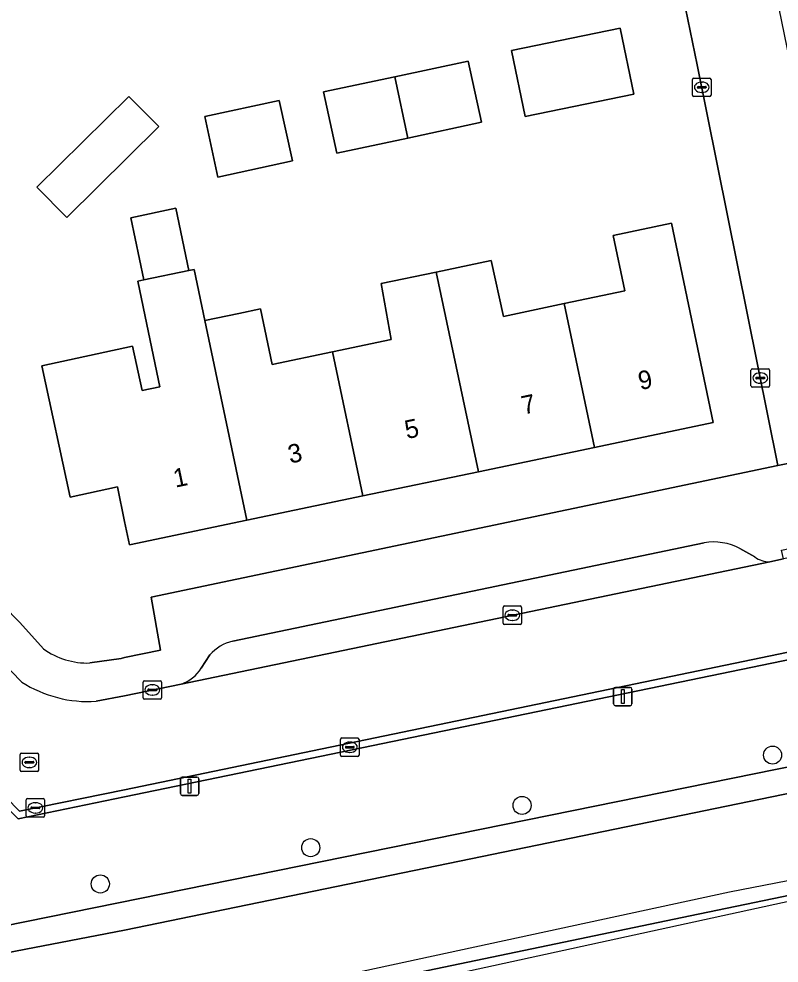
# Model space of a CAD drawing. Extents: x 162879 to 165540, y 384011 to 385181.
# Drawn here: x 163994.3 to 164035.4, y 384179.7 to 384230.8 of the extents above; entities that cross this region are included whole.
import ezdxf

# ---------------------------------------------------------------- set-up
doc = ezdxf.new("R2010")
doc.units = 0
for name, color, linetype in [('IMGEO_Boom', 7, 'Continuous'), ('IMGEO_Erf', 7, 'Continuous'), ('IMGEO_Geluidsscherm', 7, 'Continuous'), ('IMGEO_Groenvoorziening', 7, 'Continuous'), ('IMGEO_Hek', 7, 'Continuous'), ('IMGEO_Kolk', 7, 'Continuous'), ('IMGEO_Lichtmast', 7, 'Continuous'), ('IMGEO_Pand', 7, 'Continuous'), ('IMGEO_Pand_nummerreeks', 7, 'Continuous'), ('IMGEO_Parkeervlak_open', 7, 'Continuous'), ('IMGEO_Rijbaan_lokaal_open', 7, 'Continuous'), ('IMGEO_Rioolput', 7, 'Continuous'), ('IMGEO_Spoorbaan_halfverhard', 7, 'Continuous'), ('IMGEO_Voetpad_open', 7, 'Continuous')]:
    doc.layers.add(name, color=color, linetype=linetype)

msp = doc.modelspace()

# ---------------------------------------------------------------- linework, layer by layer
at = {"layer": 'IMGEO_Boom'}
for centre in [(164035.048, 384190.943), (164021.499, 384188.217), (164010.068, 384185.932), (163998.687, 384183.967)]:
    msp.add_circle(centre, 0.489, dxfattribs=at)
at = {"layer": 'IMGEO_Erf'}
for points in [[(163998.128, 384195.926), (163999.82, 384196.177), (164000, 384196.214), (164001.949, 384196.619), (164001.432, 384199.492), (164035.326, 384206.609), (164030.966, 384228.287), (164030.221, 384231.993), (164030.024, 384232.973), (164025.891, 384232.23), (164024.866, 384233.172), (164020.603, 384237.498)], [(163991.514, 384230.806), (163992.767, 384225.971), (163990.535, 384223.775), (163989.018, 384225.098), (163987.035, 384223.137), (163984.673, 384225.525), (163982.432, 384223.309), (163980.176, 384221.078), (163982.517, 384218.711), (163981.927, 384218.127), (163978.371, 384214.611), (163978.245, 384214.739), (163978.172, 384214.67), (163984.509, 384208.134), (163994.326, 384198.122), (163995.611, 384196.7)]]:
    msp.add_lwpolyline(points, dxfattribs=at)
for points in [[(164026.81, 384230.281), (164027.548, 384226.704), (164021.672, 384225.491), (164020.934, 384229.068)], [(164018.592, 384228.499), (164019.301, 384225.185), (164015.319, 384224.333), (164011.476, 384223.51), (164010.767, 384226.824), (164014.618, 384227.648)], [(164001.844, 384224.953), (163996.873, 384220.038), (163995.26, 384221.669), (164000.231, 384226.584)], [(164009.075, 384223.094), (164005.045, 384222.219), (164004.334, 384225.495), (164008.364, 384226.37)], [(164026.428, 384219.065), (164029.576, 384219.725), (164031.839, 384208.942), (164025.412, 384207.593), (164019.139, 384206.276), (164012.881, 384204.963), (164006.619, 384203.649), (164000.265, 384202.315), (164000, 384203.589), (163999.613, 384205.451), (163997.059, 384204.896), (163995.516, 384212.008), (164000.432, 384213.074), (164000.955, 384210.665), (164001.909, 384210.863), (164001.289, 384213.817), (164000.708, 384216.585), (164001.048, 384216.657), (164000.342, 384220.023), (164002.773, 384220.533), (164003.48, 384217.167), (164003.755, 384217.225), (164004.339, 384214.458), (164006.183, 384214.845), (164007.36, 384215.092), (164007.991, 384212.087), (164011.242, 384212.769), (164014.418, 384213.435), (164013.875, 384216.457), (164016.853, 384217.082), (164019.835, 384217.707), (164020.497, 384214.682), (164023.785, 384215.372), (164027.058, 384216.059)]]:
    msp.add_lwpolyline(points, close=True, dxfattribs=at)
msp.add_arc((163997.992, 384199.963), 4.039, 233.8811, 271.9327, dxfattribs=at)
at = {"layer": 'IMGEO_Geluidsscherm'}
msp.add_lwpolyline([(164249.574, 384228.544), (164187.192, 384215.485), (164162.302, 384210.469), (164148.545, 384207.416), (164111.054, 384199.697), (164098.433, 384197.191), (164085.381, 384194.319), (164046.457, 384186.201), (164032.718, 384183.532), (164006.753, 384177.923), (163992.535, 384174.933), (163980.798, 384172.554), (163968.077, 384170.103), (163956.144, 384167.447), (163943.692, 384164.81), (163915.585, 384159)], dxfattribs=at)
at = {"layer": 'IMGEO_Groenvoorziening'}
for points in [[(164160.958, 384209.557), (164249.738, 384228.363), (164257.439, 384229.994), (164258.307, 384234.301), (164257.821, 384235.374), (164247.659, 384233.092), (164206.397, 384224.477), (164195.144, 384222.287), (164168.08, 384216.522), (164150.94, 384212.716), (164150.871, 384211.974), (164045.253, 384190.792), (164000, 384181.465), (163991.655, 384179.863), (163957.137, 384215.862)], [(163910.141, 384165.293), (163907.388, 384161.891), (163904.144, 384157.751), (163904.294, 384156.793), (163905.524, 384156.297), (163907.829, 384156.853), (163915.94, 384158.516), (163963.608, 384168.288), (164030.584, 384182.247), (164064.865, 384189.352), (164113.541, 384199.968), (164160.958, 384209.557)]]:
    msp.add_lwpolyline(points, dxfattribs=at)
for points in [[(164151.264, 384223.068), (164151.207, 384224.522), (164151.782, 384230.115), (164144.063, 384233.478), (164143.197, 384222.298), (164142.818, 384218.333), (164141.152, 384217.855), (164120.789, 384213.646), (164115.149, 384212.48), (164021.738, 384193.17), (164000, 384188.678), (163994.239, 384187.487), (163984.24, 384197.653), (163961.899, 384220.601), (163959.515, 384218.234), (163957.137, 384215.862), (163991.655, 384179.863), (163992.185, 384181.427), (164150.97, 384213.664)], [(164150.871, 384211.974), (164150.94, 384212.716), (164150.953, 384213.129), (164150.97, 384213.664), (163992.185, 384181.427), (163991.655, 384179.863), (164000, 384181.465), (164045.253, 384190.792)]]:
    msp.add_lwpolyline(points, close=True, dxfattribs=at)
at = {"layer": 'IMGEO_Hek'}
for points in [[(164000, 384181.465), (164045.253, 384190.792), (164150.871, 384211.974), (164150.94, 384212.716)], [(164064.865, 384189.352), (164030.584, 384182.247), (163963.608, 384168.288), (163907.829, 384156.853), (163905.524, 384156.297), (163904.294, 384156.793), (163904.144, 384157.751)], [(164000, 384181.465), (163991.655, 384179.863)]]:
    msp.add_lwpolyline(points, dxfattribs=at)
at = {"layer": 'IMGEO_Kolk'}
for p, q in [((164030.721, 384226.653), (164030.721, 384227.505)), ((164030.796, 384227.579), (164031.648, 384227.579)), ((164031.209, 384227.359), (164031.234, 384227.359)), ((164031.722, 384227.505), (164031.722, 384226.653)), ((164030.98, 384227.073), (164030.98, 384227.085)), ((164031.418, 384227.036), (164031.02, 384227.036)), ((164031.023, 384227.122), (164031.421, 384227.122)), ((164031.232, 384226.799), (164031.207, 384226.799)), ((164031.464, 384227.085), (164031.464, 384227.073)), ((164031.648, 384226.579), (164030.796, 384226.579)), ((164033.882, 384210.92), (164033.882, 384211.772)), ((164033.957, 384211.846), (164034.809, 384211.846)), ((164034.184, 384211.389), (164034.582, 384211.389)), ((164034.37, 384211.626), (164034.395, 384211.626)), ((164034.883, 384211.772), (164034.883, 384210.92)), ((164034.141, 384211.34), (164034.141, 384211.352)), ((164034.579, 384211.303), (164034.181, 384211.303)), ((164034.393, 384211.066), (164034.368, 384211.066)), ((164034.625, 384211.352), (164034.625, 384211.34)), ((164034.809, 384210.846), (164033.957, 384210.846)), ((164020.476, 384198.085), (164020.476, 384198.937)), ((164020.551, 384199.011), (164021.403, 384199.011)), ((164020.964, 384198.791), (164020.989, 384198.791)), ((164021.477, 384198.937), (164021.477, 384198.085)), ((164020.735, 384198.505), (164020.735, 384198.517)), ((164021.173, 384198.468), (164020.775, 384198.468)), ((164020.778, 384198.554), (164021.176, 384198.554)), ((164020.987, 384198.231), (164020.962, 384198.231)), ((164021.219, 384198.517), (164021.219, 384198.505)), ((164021.403, 384198.011), (164020.551, 384198.011)), ((164001.004, 384194.042), (164001.004, 384194.894)), ((164001.079, 384194.968), (164001.931, 384194.968)), ((164001.492, 384194.748), (164001.517, 384194.748)), ((164002.005, 384194.894), (164002.005, 384194.042)), ((164001.263, 384194.462), (164001.263, 384194.474)), ((164001.701, 384194.425), (164001.303, 384194.425)), ((164001.306, 384194.511), (164001.704, 384194.511)), ((164001.515, 384194.188), (164001.49, 384194.188)), ((164001.747, 384194.474), (164001.747, 384194.462)), ((164001.931, 384193.968), (164001.079, 384193.968)), ((164011.682, 384190.942), (164011.682, 384191.794)), ((164011.757, 384191.868), (164012.609, 384191.868)), ((164012.17, 384191.648), (164012.195, 384191.648)), ((164012.683, 384191.794), (164012.683, 384190.942)), ((164011.941, 384191.362), (164011.941, 384191.374)), ((164012.379, 384191.325), (164011.981, 384191.325)), ((164011.984, 384191.411), (164012.382, 384191.411)), ((164012.193, 384191.088), (164012.168, 384191.088)), ((164012.425, 384191.374), (164012.425, 384191.362)), ((164012.609, 384190.868), (164011.757, 384190.868)), ((163994.676, 384187.661), (163994.676, 384188.513)), ((163994.751, 384188.587), (163995.603, 384188.587)), ((163995.677, 384188.513), (163995.677, 384187.661)), ((163994.935, 384188.081), (163994.935, 384188.093)), ((163995.373, 384188.044), (163994.975, 384188.044)), ((163994.978, 384188.13), (163995.376, 384188.13)), ((163995.164, 384188.367), (163995.189, 384188.367)), ((163995.419, 384188.093), (163995.419, 384188.081)), ((163995.603, 384187.587), (163994.751, 384187.587)), ((163995.187, 384187.807), (163995.162, 384187.807))]:
    msp.add_line(p, q, dxfattribs=at)
for points in [[(164030.721, 384226.653), (164030.721, 384227.505)], [(164030.796, 384227.579), (164031.648, 384227.579)], [(164031.722, 384227.505), (164031.722, 384226.653)], [(164031.648, 384226.579), (164030.796, 384226.579)], [(164033.882, 384210.92), (164033.882, 384211.772)], [(164033.957, 384211.846), (164034.809, 384211.846)], [(164034.883, 384211.772), (164034.883, 384210.92)], [(164034.809, 384210.846), (164033.957, 384210.846)], [(164020.476, 384198.085), (164020.476, 384198.937)], [(164020.551, 384199.011), (164021.403, 384199.011)], [(164021.477, 384198.937), (164021.477, 384198.085)], [(164021.403, 384198.011), (164020.551, 384198.011)], [(164001.004, 384194.042), (164001.004, 384194.894)], [(164001.079, 384194.968), (164001.931, 384194.968)], [(164002.005, 384194.894), (164002.005, 384194.042)], [(164001.931, 384193.968), (164001.079, 384193.968)], [(164011.682, 384190.942), (164011.682, 384191.794)], [(164011.757, 384191.868), (164012.609, 384191.868)], [(164012.683, 384191.794), (164012.683, 384190.942)], [(164012.609, 384190.868), (164011.757, 384190.868)], [(163994.676, 384187.661), (163994.676, 384188.513)], [(163994.751, 384188.587), (163995.603, 384188.587)], [(163995.677, 384188.513), (163995.677, 384187.661)], [(163995.603, 384187.587), (163994.751, 384187.587)]]:
    msp.add_lwpolyline(points, dxfattribs=at)
for centre, radius, start, end in [((164030.798, 384227.503), 0.0765, 91.552, 178.448), ((164030.798, 384227.503), 0.0765, 91.552, 178.448), ((164031.646, 384227.503), 0.0765, 1.552, 88.448), ((164031.646, 384227.503), 0.0765, 1.552, 88.448), ((164031.02, 384227.082), 0.0403, 85.8775, 175.7526), ((164031.017, 384227.072), 0.0366, 178.938, 274.7102), ((164031.421, 384227.079), 0.043, 264.8664, 352.4533), ((164031.425, 384227.084), 0.0386, 1.7309, 96.639), ((164030.798, 384226.655), 0.0765, 181.552, 268.448), ((164030.798, 384226.655), 0.0765, 181.552, 268.448), ((164031.646, 384226.655), 0.0765, 271.552, 358.448), ((164031.646, 384226.655), 0.0765, 271.552, 358.448), ((164033.959, 384211.77), 0.0765, 91.552, 178.448), ((164033.959, 384211.77), 0.0765, 91.552, 178.448), ((164034.181, 384211.349), 0.0403, 85.8775, 175.7526), ((164034.586, 384211.351), 0.0386, 1.7309, 96.639), ((164034.807, 384211.77), 0.0765, 1.552, 88.448), ((164034.807, 384211.77), 0.0765, 1.552, 88.448), ((164033.959, 384210.922), 0.0765, 181.552, 268.448), ((164033.959, 384210.922), 0.0765, 181.552, 268.448), ((164034.178, 384211.339), 0.0366, 178.938, 274.7102), ((164034.582, 384211.346), 0.043, 264.8664, 352.4533), ((164034.807, 384210.922), 0.0765, 271.552, 358.448), ((164034.807, 384210.922), 0.0765, 271.552, 358.448), ((164020.553, 384198.935), 0.0765, 91.552, 178.448), ((164020.553, 384198.935), 0.0765, 91.552, 178.448), ((164021.401, 384198.935), 0.0765, 1.552, 88.448), ((164021.401, 384198.935), 0.0765, 1.552, 88.448), ((164020.775, 384198.514), 0.0403, 85.8775, 175.7526), ((164020.772, 384198.504), 0.0366, 178.938, 274.7102), ((164021.176, 384198.511), 0.043, 264.8664, 352.4533), ((164021.18, 384198.516), 0.0386, 1.7309, 96.639), ((164020.553, 384198.087), 0.0765, 181.552, 268.448), ((164020.553, 384198.087), 0.0765, 181.552, 268.448), ((164021.401, 384198.087), 0.0765, 271.552, 358.448), ((164021.401, 384198.087), 0.0765, 271.552, 358.448), ((164001.081, 384194.892), 0.0765, 91.552, 178.448), ((164001.081, 384194.892), 0.0765, 91.552, 178.448), ((164001.929, 384194.892), 0.0765, 1.552, 88.448), ((164001.929, 384194.892), 0.0765, 1.552, 88.448), ((164001.081, 384194.044), 0.0765, 181.552, 268.448), ((164001.081, 384194.044), 0.0765, 181.552, 268.448), ((164001.303, 384194.471), 0.0403, 85.8775, 175.7526), ((164001.3, 384194.461), 0.0366, 178.938, 274.7102), ((164001.704, 384194.468), 0.043, 264.8664, 352.4533), ((164001.708, 384194.473), 0.0386, 1.7309, 96.639), ((164001.929, 384194.044), 0.0765, 271.552, 358.448), ((164001.929, 384194.044), 0.0765, 271.552, 358.448), ((164011.759, 384191.792), 0.0765, 91.552, 178.448), ((164011.759, 384191.792), 0.0765, 91.552, 178.448), ((164012.607, 384191.792), 0.0765, 1.552, 88.448), ((164012.607, 384191.792), 0.0765, 1.552, 88.448), ((164011.759, 384190.944), 0.0765, 181.552, 268.448), ((164011.759, 384190.944), 0.0765, 181.552, 268.448), ((164011.981, 384191.371), 0.0403, 85.8775, 175.7526), ((164011.978, 384191.361), 0.0366, 178.938, 274.7102), ((164012.382, 384191.368), 0.043, 264.8664, 352.4533), ((164012.386, 384191.373), 0.0386, 1.7309, 96.639), ((164012.607, 384190.944), 0.0765, 271.552, 358.448), ((164012.607, 384190.944), 0.0765, 271.552, 358.448), ((163994.753, 384188.511), 0.0765, 91.552, 178.448), ((163994.753, 384188.511), 0.0765, 91.552, 178.448), ((163995.601, 384188.511), 0.0765, 1.552, 88.448), ((163995.601, 384188.511), 0.0765, 1.552, 88.448), ((163994.975, 384188.09), 0.0403, 85.8775, 175.7526), ((163994.972, 384188.08), 0.0366, 178.938, 274.7102), ((163995.376, 384188.087), 0.043, 264.8664, 352.4533), ((163995.38, 384188.092), 0.0386, 1.7309, 96.639), ((163994.753, 384187.663), 0.0765, 181.552, 268.448), ((163994.753, 384187.663), 0.0765, 181.552, 268.448), ((163995.601, 384187.663), 0.0765, 271.552, 358.448), ((163995.601, 384187.663), 0.0765, 271.552, 358.448)]:
    msp.add_arc(centre, radius, start, end, dxfattribs=at)
for centre, major_axis, ratio, start_param, end_param in [((164031.208, 384227.079), (-0.387, 0.002), 0.722429, 4.712389, 7.853982), ((164031.233, 384227.079), (-0.39, 0.002), 0.717154, 1.570796, 4.712389), ((164034.369, 384211.346), (-0.387, 0.002), 0.722429, 4.712389, 7.853982), ((164034.394, 384211.346), (-0.39, 0.002), 0.717154, 1.570796, 4.712389), ((164020.963, 384198.511), (-0.387, 0.002), 0.722429, 4.712389, 7.853982), ((164020.988, 384198.511), (-0.39, 0.002), 0.717154, 1.570796, 4.712389), ((164001.491, 384194.468), (-0.387, 0.002), 0.722429, 4.712389, 7.853982), ((164001.516, 384194.468), (-0.39, 0.002), 0.717154, 1.570796, 4.712389), ((164012.169, 384191.368), (-0.387, 0.002), 0.722429, 4.712389, 7.853982), ((164012.194, 384191.368), (-0.39, 0.002), 0.717154, 1.570796, 4.712389), ((163995.163, 384188.087), (-0.387, 0.002), 0.722429, 4.712389, 7.853982), ((163995.188, 384188.087), (-0.39, 0.002), 0.717154, 1.570796, 4.712389)]:
    msp.add_ellipse(centre, major_axis=major_axis, ratio=ratio, start_param=start_param, end_param=end_param, dxfattribs=at)
at = {"layer": 'IMGEO_Lichtmast'}
for p, q in [((164026.553, 384194.608), (164027.343, 384194.608)), ((164027.343, 384194.608), (164026.553, 384194.608)), ((164026.453, 384193.708), (164026.453, 384194.508)), ((164026.453, 384194.508), (164026.453, 384193.708)), ((164027.443, 384194.508), (164027.443, 384193.708)), ((164027.443, 384193.708), (164027.443, 384194.508)), ((164027.343, 384193.608), (164026.553, 384193.608)), ((164026.553, 384193.608), (164027.343, 384193.608)), ((164003.021, 384188.856), (164003.021, 384189.656)), ((164003.021, 384189.656), (164003.021, 384188.856)), ((164003.121, 384189.756), (164003.911, 384189.756)), ((164003.911, 384189.756), (164003.121, 384189.756)), ((164004.011, 384189.656), (164004.011, 384188.856)), ((164004.011, 384188.856), (164004.011, 384189.656)), ((164003.911, 384188.756), (164003.121, 384188.756)), ((164003.121, 384188.756), (164003.911, 384188.756))]:
    msp.add_line(p, q, dxfattribs=at)
for points in [[(164026.873, 384194.483), (164027.023, 384194.483), (164027.023, 384193.733), (164026.873, 384193.733), (164026.873, 384194.483)], [(164003.441, 384189.631), (164003.591, 384189.631), (164003.591, 384188.881), (164003.441, 384188.881), (164003.441, 384189.631)]]:
    msp.add_lwpolyline(points, dxfattribs=at)
for centre, start, end in [((164026.553, 384194.508), 90, 180), ((164026.553, 384194.508), 90, 180), ((164027.343, 384194.508), 0, 90), ((164027.343, 384194.508), 360, 90), ((164026.553, 384193.708), 180, 270), ((164026.553, 384193.708), 180, 270), ((164027.343, 384193.708), 270, 0), ((164027.343, 384193.708), 270, 0), ((164003.121, 384189.656), 90, 180), ((164003.121, 384189.656), 90, 180), ((164003.911, 384189.656), 0, 90), ((164003.911, 384189.656), 360, 90), ((164003.121, 384188.856), 180, 270), ((164003.121, 384188.856), 180, 270), ((164003.911, 384188.856), 270, 0), ((164003.911, 384188.856), 270, 0)]:
    msp.add_arc(centre, 0.1, start, end, dxfattribs=at)
at = {"layer": 'IMGEO_Pand'}
for points in [[(164021.672, 384225.491), (164027.548, 384226.704), (164026.81, 384230.281), (164020.934, 384229.068)], [(164015.319, 384224.333), (164019.301, 384225.185), (164018.592, 384228.499), (164014.618, 384227.648)], [(164015.319, 384224.333), (164014.618, 384227.648), (164010.767, 384226.824), (164011.476, 384223.51)], [(164001.844, 384224.953), (164000.231, 384226.584), (163995.26, 384221.669), (163996.873, 384220.038)], [(164008.364, 384226.37), (164004.334, 384225.495), (164005.045, 384222.219), (164009.075, 384223.094)], [(164001.048, 384216.657), (164003.48, 384217.167), (164002.773, 384220.533), (164000.342, 384220.023)], [(164025.412, 384207.593), (164031.839, 384208.942), (164029.576, 384219.725), (164026.428, 384219.065), (164027.058, 384216.059), (164023.785, 384215.372)], [(164019.139, 384206.276), (164025.412, 384207.593), (164023.785, 384215.372), (164020.497, 384214.682), (164019.835, 384217.707), (164016.853, 384217.082)], [(164004.339, 384214.458), (164003.755, 384217.225), (164003.48, 384217.167), (164001.048, 384216.657), (164000.708, 384216.585), (164001.289, 384213.817), (164001.909, 384210.863), (164000.955, 384210.665), (164000.432, 384213.074), (163995.516, 384212.008), (163997.059, 384204.896), (163999.613, 384205.451), (164000, 384203.589), (164000.265, 384202.315), (164006.619, 384203.649)], [(164012.881, 384204.963), (164019.139, 384206.276), (164016.853, 384217.082), (164013.875, 384216.457), (164014.418, 384213.435), (164011.242, 384212.769)], [(164006.619, 384203.649), (164012.881, 384204.963), (164011.242, 384212.769), (164007.991, 384212.087), (164007.36, 384215.092), (164006.183, 384214.845), (164004.339, 384214.458)]]:
    msp.add_lwpolyline(points, close=True, dxfattribs=at)
at = {"layer": 'IMGEO_Parkeervlak_open'}
for points in [[(164031.352, 384202.433), (164005.852, 384197.102)], [(164034.085, 384201.67), (164033.283, 384202.124)], [(164003.053, 384194.788), (164034.909, 384201.404)], [(164004.619, 384196.36), (164004.144, 384195.647)]]:
    msp.add_lwpolyline(points, dxfattribs=at)
for centre, radius, start, end in [((164031.854, 384199.38), 3.094, 62.4861, 99.3311), ((164034.871, 384202.696), 1.293, 232.5473, 271.6709), ((164006.284, 384194.989), 2.157, 101.55, 140.5277), ((164002.448, 384196.679), 1.986, 287.7495, 328.6808)]:
    msp.add_arc(centre, radius, start, end, dxfattribs=at)
at = {"layer": 'IMGEO_Rijbaan_lokaal_open'}
for points in [[(164030.221, 384231.993), (164030.966, 384228.287), (164035.326, 384206.609), (164040.268, 384207.587), (164034.815, 384234.262)], [(163994.44, 384194.894), (163985.824, 384203.771), (163983.165, 384206.511), (163965.842, 384224.417), (163962.145, 384220.88), (163994.317, 384187.915), (164000, 384189.057), (164065.439, 384202.652), (164115.052, 384212.95)], [(164087.037, 384212.228), (164041.457, 384202.763), (164035.631, 384201.554), (164034.909, 384201.404), (164003.053, 384194.788), (164000, 384194.155), (163998.457, 384193.852)]]:
    msp.add_lwpolyline(points, dxfattribs=at)
msp.add_arc((163998.037, 384200.495), 6.656, 237.2944, 273.6218, dxfattribs=at)
at = {"layer": 'IMGEO_Rioolput'}
for p, q in [((163994.352, 384190.122), (163994.352, 384190.974)), ((163994.427, 384191.048), (163995.279, 384191.048)), ((163995.353, 384190.974), (163995.353, 384190.122)), ((163994.611, 384190.542), (163994.611, 384190.554)), ((163995.049, 384190.505), (163994.651, 384190.505)), ((163994.654, 384190.591), (163995.052, 384190.591)), ((163994.84, 384190.828), (163994.865, 384190.828)), ((163995.095, 384190.554), (163995.095, 384190.542)), ((163995.279, 384190.048), (163994.427, 384190.048)), ((163994.863, 384190.268), (163994.838, 384190.268))]:
    msp.add_line(p, q, dxfattribs=at)
for points in [[(163994.352, 384190.122), (163994.352, 384190.974)], [(163994.427, 384191.048), (163995.279, 384191.048)], [(163995.353, 384190.974), (163995.353, 384190.122)], [(163995.279, 384190.048), (163994.427, 384190.048)]]:
    msp.add_lwpolyline(points, dxfattribs=at)
for centre, radius, start, end in [((163994.429, 384190.972), 0.0765, 91.552, 178.448), ((163994.429, 384190.972), 0.0765, 91.552, 178.448), ((163995.277, 384190.972), 0.0765, 1.552, 88.448), ((163995.277, 384190.972), 0.0765, 1.552, 88.448), ((163994.651, 384190.551), 0.0403, 85.8775, 175.7526), ((163994.648, 384190.541), 0.0366, 178.938, 274.7102), ((163995.052, 384190.548), 0.043, 264.8664, 352.4533), ((163995.056, 384190.553), 0.0386, 1.7309, 96.639), ((163994.429, 384190.124), 0.0765, 181.552, 268.448), ((163994.429, 384190.124), 0.0765, 181.552, 268.448), ((163995.277, 384190.124), 0.0765, 271.552, 358.448), ((163995.277, 384190.124), 0.0765, 271.552, 358.448)]:
    msp.add_arc(centre, radius, start, end, dxfattribs=at)
for centre, major_axis, ratio, start_param, end_param in [((163994.839, 384190.548), (-0.387, 0.002), 0.722429, 4.712389, 7.853982), ((163994.864, 384190.548), (-0.39, 0.002), 0.717154, 1.570796, 4.712389)]:
    msp.add_ellipse(centre, major_axis=major_axis, ratio=ratio, start_param=start_param, end_param=end_param, dxfattribs=at)
at = {"layer": 'IMGEO_Spoorbaan_halfverhard'}
msp.add_lwpolyline([(163901.227, 384153.87), (163913.021, 384156.381), (163941.114, 384162.363), (164064.865, 384189.352), (164030.584, 384182.247), (163963.608, 384168.288), (163915.94, 384158.516), (163907.829, 384156.853), (163905.524, 384156.297), (163904.294, 384156.793), (163904.144, 384157.751), (163904.122, 384157.722), (163904.031, 384157.6), (163903.851, 384157.361), (163903.239, 384156.547), (163901.227, 384153.87)], close=True, dxfattribs=at)
at = {"layer": 'IMGEO_Voetpad_open'}
for points in [[(163995.611, 384196.7), (163994.326, 384198.122), (163984.509, 384208.134), (163978.172, 384214.67), (163977.839, 384214.354), (163966.931, 384225.593), (163965.842, 384224.417), (163983.165, 384206.511), (163983.468, 384206.809), (163986.147, 384204.09), (163985.824, 384203.771), (163994.44, 384194.894)], [(164034.909, 384201.404), (164035.631, 384201.554), (164035.534, 384202.034), (164041.36, 384203.241), (164041.457, 384202.763), (164087.037, 384212.228)], [(164064.975, 384209.771), (164046.584, 384206.117), (164042.602, 384205.282), (164041.964, 384207.981), (164041.92, 384208.166), (164040.268, 384207.587), (164035.326, 384206.609), (164001.432, 384199.492), (164001.949, 384196.619), (164000, 384196.214), (163999.82, 384196.177), (163998.128, 384195.926)], [(164005.852, 384197.102), (164031.352, 384202.433)], [(164033.283, 384202.124), (164034.085, 384201.67)], [(164004.144, 384195.647), (164004.619, 384196.36)], [(163998.457, 384193.852), (164000, 384194.155), (164003.053, 384194.788)]]:
    msp.add_lwpolyline(points, dxfattribs=at)
msp.add_lwpolyline([(164115.149, 384212.48), (164115.052, 384212.95), (164065.439, 384202.652), (164000, 384189.057), (163994.317, 384187.915), (163962.145, 384220.88), (163961.899, 384220.601), (163984.24, 384197.653), (163994.239, 384187.487), (164000, 384188.678), (164021.738, 384193.17)], close=True, dxfattribs=at)
for centre, radius, start, end in [((164031.854, 384199.38), 3.094, 62.4861, 99.3311), ((164034.871, 384202.696), 1.293, 232.5473, 271.6709), ((164006.284, 384194.989), 2.157, 101.55, 140.5277), ((163997.992, 384199.963), 4.039, 233.8811, 271.9327), ((164002.448, 384196.679), 1.986, 287.7495, 328.6808), ((163998.037, 384200.495), 6.656, 237.2944, 273.6218)]:
    msp.add_arc(centre, radius, start, end, dxfattribs=at)

# ---------------------------------------------------------------- texts
at = {"layer": 'IMGEO_Pand_nummerreeks'}
for s, rotation, p in [('9', 11.8536, (164027.894, 384210.689)), ('7', 11.8536, (164021.579, 384209.364)), ('5', 11.8536, (164015.264, 384208.039)), ('3', 11.8536, (164008.95, 384206.713)), ('1', 11.8545, (164002.747, 384205.41))]:
    msp.add_text(s, height=1, rotation=rotation, dxfattribs=at).set_placement(p)

doc.saveas('drawing.dxf')
